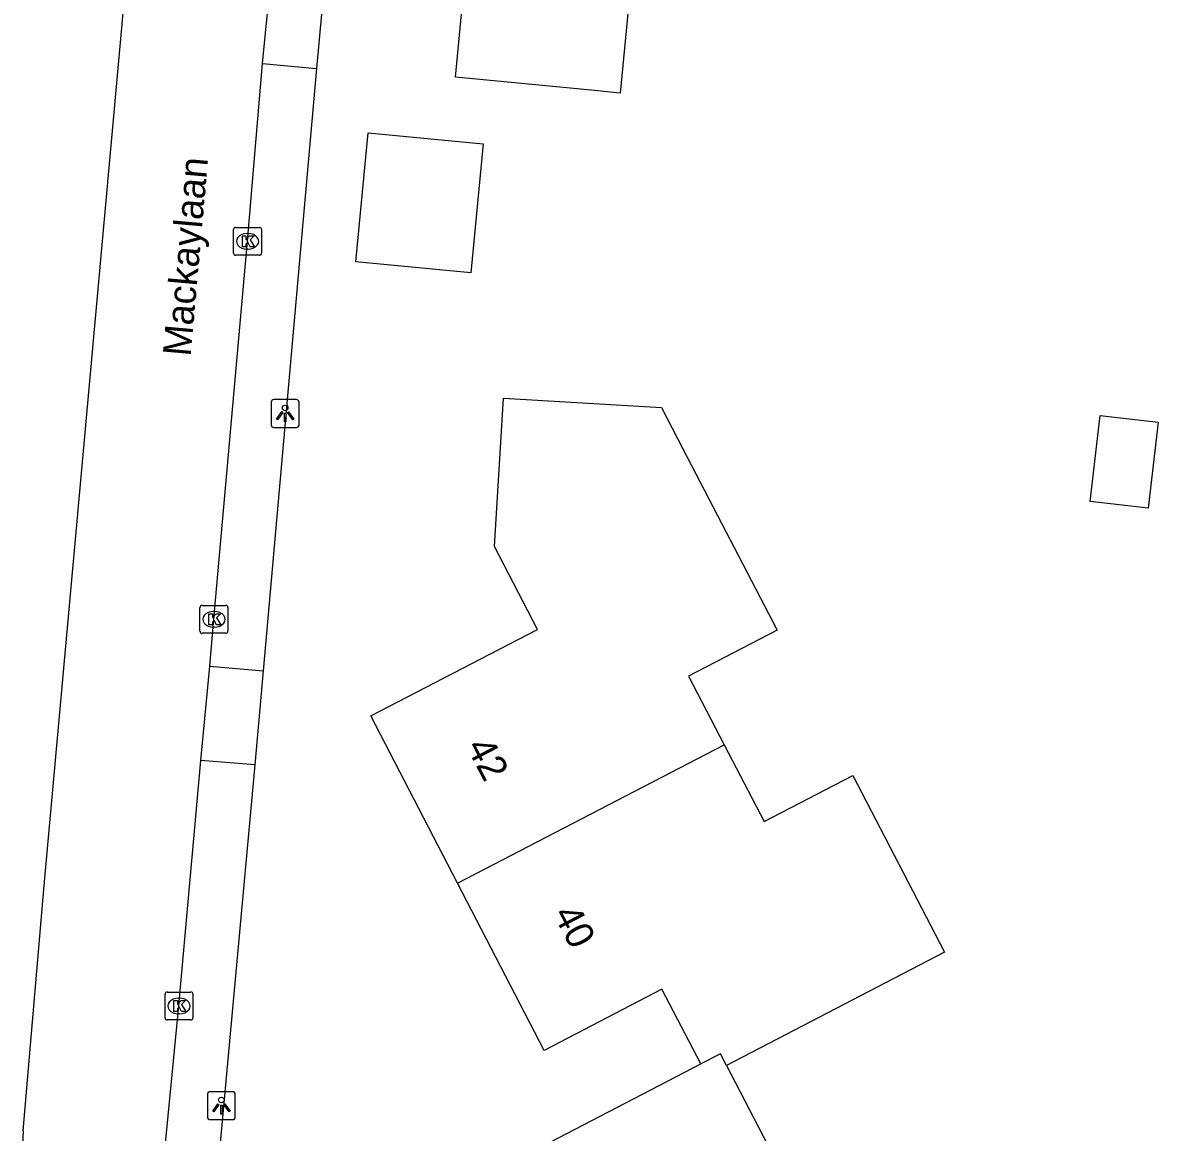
# Model space of a CAD drawing. Extents: x 162722 to 165099, y 384721 to 386283.
# Drawn here: x 163875.08 to 163915.74, y 385123.99 to 385163.71 of the extents above; entities that cross this region are included whole.
import ezdxf

# ---------------------------------------------------------------- set-up
doc = ezdxf.new("R2010")
doc.units = 0
for name, color, linetype in [('IMGEO_Kolk', 7, 'Continuous'), ('IMGEO_Lichtpunt', 7, 'Continuous'), ('IMGEO_Openbare_ruimte_label', 7, 'Continuous'), ('IMGEO_Pand', 7, 'Continuous'), ('IMGEO_Pand_nummerreeks', 7, 'Continuous'), ('IMGEO_Rijbaan_lokaal_open', 7, 'Continuous'), ('IMGEO_Voetpad_open', 7, 'Continuous')]:
    doc.layers.add(name, color=color, linetype=linetype)

msp = doc.modelspace()

# ---------------------------------------------------------------- linework, layer by layer
at = {"layer": 'IMGEO_Kolk'}
for p, q in [((163882.628, 385155.459), (163882.628, 385156.311)), ((163882.703, 385156.385), (163883.555, 385156.385)), ((163883.116, 385156.165), (163883.141, 385156.165)), ((163883.629, 385156.311), (163883.629, 385155.459)), ((163883.555, 385155.385), (163882.703, 385155.385)), ((163883.139, 385155.605), (163883.114, 385155.605)), ((163881.425, 385141.925), (163881.425, 385142.777)), ((163881.5, 385142.851), (163882.352, 385142.851)), ((163882.426, 385142.777), (163882.426, 385141.925)), ((163881.913, 385142.631), (163881.938, 385142.631)), ((163881.936, 385142.071), (163881.911, 385142.071)), ((163882.352, 385141.851), (163881.5, 385141.851)), ((163880.172, 385128.082), (163880.172, 385128.934)), ((163880.247, 385129.008), (163881.099, 385129.008)), ((163881.173, 385128.934), (163881.173, 385128.082)), ((163880.66, 385128.788), (163880.685, 385128.788)), ((163880.683, 385128.228), (163880.658, 385128.228)), ((163881.099, 385128.008), (163880.247, 385128.008))]:
    msp.add_line(p, q, dxfattribs=at)
for points in [[(163882.628, 385155.459), (163882.628, 385156.311)], [(163882.703, 385156.385), (163883.555, 385156.385)], [(163883.629, 385156.311), (163883.629, 385155.459)], [(163882.949, 385156.085), (163883.072, 385156.085), (163883.072, 385155.934), (163883.202, 385156.085), (163883.366, 385156.085), (163883.22, 385155.934), (163883.373, 385155.685), (163883.221, 385155.685), (163883.136, 385155.849), (163883.072, 385155.782), (163883.072, 385155.685), (163882.949, 385155.685), (163882.949, 385156.085)], [(163883.555, 385155.385), (163882.703, 385155.385)], [(163881.425, 385141.925), (163881.425, 385142.777)], [(163881.5, 385142.851), (163882.352, 385142.851)], [(163882.426, 385142.777), (163882.426, 385141.925)], [(163881.746, 385142.551), (163881.869, 385142.551), (163881.869, 385142.4), (163881.999, 385142.551), (163882.163, 385142.551), (163882.017, 385142.4), (163882.17, 385142.151), (163882.018, 385142.151), (163881.933, 385142.315), (163881.869, 385142.248), (163881.869, 385142.151), (163881.746, 385142.151), (163881.746, 385142.551)], [(163882.352, 385141.851), (163881.5, 385141.851)], [(163880.172, 385128.082), (163880.172, 385128.934)], [(163880.247, 385129.008), (163881.099, 385129.008)], [(163881.173, 385128.934), (163881.173, 385128.082)], [(163880.493, 385128.708), (163880.616, 385128.708), (163880.616, 385128.557), (163880.746, 385128.708), (163880.91, 385128.708), (163880.764, 385128.557), (163880.917, 385128.308), (163880.765, 385128.308), (163880.68, 385128.472), (163880.616, 385128.405), (163880.616, 385128.308), (163880.493, 385128.308), (163880.493, 385128.708)], [(163881.099, 385128.008), (163880.247, 385128.008)]]:
    msp.add_lwpolyline(points, dxfattribs=at)
for centre, start, end in [((163882.705, 385156.309), 91.552, 178.448), ((163882.705, 385156.309), 91.552, 178.448), ((163883.553, 385156.309), 1.552, 88.448), ((163883.553, 385156.309), 1.552, 88.448), ((163882.705, 385155.461), 181.552, 268.448), ((163882.705, 385155.461), 181.552, 268.448), ((163883.553, 385155.461), 271.552, 358.448), ((163883.553, 385155.461), 271.552, 358.448), ((163881.502, 385142.775), 91.552, 178.448), ((163881.502, 385142.775), 91.552, 178.448), ((163882.35, 385142.775), 1.552, 88.448), ((163882.35, 385142.775), 1.552, 88.448), ((163881.502, 385141.927), 181.552, 268.448), ((163881.502, 385141.927), 181.552, 268.448), ((163882.35, 385141.927), 271.552, 358.448), ((163882.35, 385141.927), 271.552, 358.448), ((163880.249, 385128.932), 91.552, 178.448), ((163880.249, 385128.932), 91.552, 178.448), ((163881.097, 385128.932), 1.552, 88.448), ((163881.097, 385128.932), 1.552, 88.448), ((163880.249, 385128.084), 181.552, 268.448), ((163880.249, 385128.084), 181.552, 268.448), ((163881.097, 385128.084), 271.552, 358.448), ((163881.097, 385128.084), 271.552, 358.448)]:
    msp.add_arc(centre, 0.0765, start, end, dxfattribs=at)
for centre, major_axis, ratio, start_param, end_param in [((163883.115, 385155.885), (-0.387, 0.002), 0.722429, 4.712389, 7.853982), ((163883.14, 385155.885), (-0.39, 0.002), 0.717154, 1.570796, 4.712389), ((163881.912, 385142.351), (-0.387, 0.002), 0.722429, 4.712389, 7.853982), ((163881.937, 385142.351), (-0.39, 0.002), 0.717154, 1.570796, 4.712389), ((163880.659, 385128.508), (-0.387, 0.002), 0.722429, 4.712389, 7.853982), ((163880.684, 385128.508), (-0.39, 0.002), 0.717154, 1.570796, 4.712389)]:
    msp.add_ellipse(centre, major_axis=major_axis, ratio=ratio, start_param=start_param, end_param=end_param, dxfattribs=at)
at = {"layer": 'IMGEO_Lichtpunt'}
for p, q in [((163883.976, 385150.122), (163883.976, 385149.315)), ((163883.976, 385150.122), (163883.976, 385149.315)), ((163884.878, 385150.217), (163884.07, 385150.217)), ((163884.878, 385150.217), (163884.07, 385150.217)), ((163884.972, 385149.315), (163884.972, 385150.122)), ((163884.972, 385149.315), (163884.972, 385150.122)), ((163884.07, 385149.221), (163884.878, 385149.221)), ((163884.07, 385149.221), (163884.878, 385149.221)), ((163881.692, 385125.343), (163881.692, 385124.536)), ((163881.692, 385125.343), (163881.692, 385124.536)), ((163882.594, 385125.438), (163881.786, 385125.438)), ((163882.594, 385125.438), (163881.786, 385125.438)), ((163882.688, 385124.536), (163882.688, 385125.343)), ((163882.688, 385124.536), (163882.688, 385125.343)), ((163881.786, 385124.442), (163882.594, 385124.442)), ((163881.786, 385124.442), (163882.594, 385124.442))]:
    msp.add_line(p, q, dxfattribs=at)
for points in [[(163884.35, 385149.786), (163884.389, 385149.758), (163884.201, 385149.496), (163884.163, 385149.523), (163884.35, 385149.786)], [(163884.452, 385149.738), (163884.499, 385149.738), (163884.499, 385149.416), (163884.452, 385149.416), (163884.452, 385149.738)], [(163884.562, 385149.758), (163884.6, 385149.785), (163884.787, 385149.523), (163884.748, 385149.495), (163884.562, 385149.758)], [(163882.066, 385125.007), (163882.105, 385124.979), (163881.917, 385124.717), (163881.879, 385124.744), (163882.066, 385125.007)], [(163882.168, 385124.959), (163882.215, 385124.959), (163882.215, 385124.637), (163882.168, 385124.637), (163882.168, 385124.959)], [(163882.278, 385124.979), (163882.316, 385125.006), (163882.503, 385124.744), (163882.464, 385124.716), (163882.278, 385124.979)]]:
    msp.add_lwpolyline(points, dxfattribs=at)
for centre in [(163884.475, 385149.92), (163882.191, 385125.141)]:
    msp.add_circle(centre, 0.0994, dxfattribs=at)
for centre, start, end in [((163884.07, 385150.122), 90, 180), ((163884.07, 385150.122), 90, 180), ((163884.878, 385150.122), 0, 90), ((163884.878, 385150.122), 0, 90), ((163884.07, 385149.315), 180, 270), ((163884.07, 385149.315), 180, 270), ((163884.878, 385149.315), 270, 0), ((163884.878, 385149.315), 270, 360), ((163881.786, 385125.343), 90, 180), ((163881.786, 385125.343), 90, 180), ((163882.594, 385125.343), 0, 90), ((163882.594, 385125.343), 0, 90), ((163881.786, 385124.536), 180, 270), ((163881.786, 385124.536), 180, 270), ((163882.594, 385124.536), 270, 0), ((163882.594, 385124.536), 270, 360)]:
    msp.add_arc(centre, 0.0946, start, end, dxfattribs=at)
at = {"layer": 'IMGEO_Pand'}
for points in [[(163890.574, 385161.758), (163891.389, 385170.298), (163889.281, 385170.499), (163890.174, 385179.851), (163903.687, 385178.562), (163903.44, 385175.97), (163906.902, 385175.64), (163906.342, 385169.766), (163902.88, 385170.096), (163897.377, 385170.621), (163896.477, 385161.194), (163895.552, 385161.282), (163890.574, 385161.758)], [(163891.128, 385154.761), (163887.006, 385155.155), (163887.447, 385159.768), (163891.569, 385159.373), (163891.128, 385154.761)], [(163890.648, 385132.902), (163887.541, 385138.892), (163891.8, 385141.101), (163893.513, 385141.989), (163891.973, 385144.959), (163892.29, 385150.271), (163897.958, 385149.932), (163898.722, 385148.46), (163902.091, 385141.966), (163898.921, 385140.321), (163900.198, 385137.859)], [(163913.301, 385146.57), (163913.665, 385149.653), (163915.743, 385149.408), (163915.38, 385146.325), (163913.301, 385146.57)], [(163890.648, 385132.902), (163900.198, 385137.859)], [(163900.198, 385137.859), (163901.623, 385135.112), (163904.803, 385136.761), (163908.087, 385130.43), (163900.283, 385126.382)], [(163899.356, 385126.431), (163897.969, 385129.104), (163893.753, 385126.917), (163890.648, 385132.902)], [(163900.283, 385126.382), (163900.067, 385126.799), (163899.356, 385126.431)], [(163892.046, 385110.996), (163888.962, 385116.942), (163893.113, 385119.095), (163894.445, 385119.786), (163892.77, 385123.015), (163899.356, 385126.431)], [(163900.283, 385126.382), (163903.401, 385120.37), (163900.274, 385118.748), (163901.698, 385116.004)]]:
    msp.add_lwpolyline(points, dxfattribs=at)
at = {"layer": 'IMGEO_Rijbaan_lokaal_open'}
for points in [[(163875.09, 385124.032), (163875.847, 385132.818), (163880.395, 385183.052), (163880.235, 385184.011)], [(163883.667, 385162.254), (163884.19, 385167.579)], [(163881.772, 385140.671), (163881.926, 385142.351), (163883.129, 385155.885), (163883.667, 385162.254)], [(163881.456, 385137.298), (163881.772, 385140.671)], [(163880.129, 385122.974), (163880.673, 385128.508), (163881.456, 385137.298)]]:
    msp.add_lwpolyline(points, dxfattribs=at)
msp.add_arc((163890.68, 385123.38), 15.604, 177.6045, 205.7007, dxfattribs=at)
at = {"layer": 'IMGEO_Voetpad_open'}
for points in [[(163886.089, 385167.412), (163885.6, 385162.073)], [(163883.667, 385162.254), (163885.6, 385162.073)], [(163885.6, 385162.073), (163883.691, 385140.51)], [(163881.772, 385140.671), (163883.691, 385140.51)], [(163883.691, 385140.51), (163883.387, 385137.136)], [(163883.387, 385137.136), (163881.456, 385137.298)], [(163883.387, 385137.136), (163882.068, 385122.686)]]:
    msp.add_lwpolyline(points, dxfattribs=at)

# ---------------------------------------------------------------- texts
at = {"layer": 'IMGEO_Openbare_ruimte_label'}
msp.add_text('Mackaylaan', height=1, rotation=84.9508, dxfattribs=at).set_placement((163881.088, 385151.743))
at = {"layer": 'IMGEO_Pand_nummerreeks'}
for s, rotation, p in [('42', 297.4158, (163890.948, 385137.796)), ('40', 297.4179, (163894.057, 385131.802))]:
    msp.add_text(s, height=1, rotation=rotation, dxfattribs=at).set_placement(p)

doc.saveas('drawing.dxf')
